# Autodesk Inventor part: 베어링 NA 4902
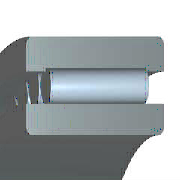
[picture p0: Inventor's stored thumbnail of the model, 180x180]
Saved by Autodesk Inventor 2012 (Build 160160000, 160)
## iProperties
IsCustomPart: 0
Manager: KYOUNG IL JANG
Company: 한국ATC센터
Created: 2009-02
Part Number: 베어링 NA 4902
Material: Steel, Mild
Description: 니들 롤러 베어링 - 경계 치수 및 공차
Document SubType Name: Modeling
Standard: KS B 2029
Standards Organization: KS
Language: ko-KR
Size Designation: NA 4902 - 15 x 28 x 13
Categories: <MemberInstance><Categories><Category DisplayName="샤프트 부품" InternalName="7f7aeb1f-a693-4053-b835-cee3144e0d98" Mnemonic="SHFT"><Category DisplayName="베어링" Inter
Density: 1 g/cm^3
Checked By: KYOUNG IL JANG
Vendor: CBT Solutions
Designer: KYOUNG IL JANG
Author: KYOUNG IL JANG
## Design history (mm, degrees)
revolve "본체" stored, may be unused: angle "d17" = 90 deg
revolve "롤러" stored, may be unused: angle "d18" = 90 deg
body "Solid1"
sketch "스케치"
  geometry: L1 (1.857, 11.5)-(11.143, 11.5); L2 (11.143, 11.5)-(11.143, 10); L3 (13, 10)-(0, 10); L4 (1.857, 10)-(1.857, 11.5); L5 (1.857, 10.75)-(11.143, 10.75); L6 (6.5, 10.75)-(6.5, 10); L7 (0, 7.5)-(13, 7.5); L8 (0, 14)-(13, 14); L9 (13, 7.5)-(13, 10); L10 (13, 11.35)-(13, 14); L11 (1.857, 11.35)-(0, 11.35); L12 (11.143, 11.35)-(13, 11.35); L13 (-6, 0)-(36, 0) reference; L14 (0, -1.9)-(0, 14.9) reference
  constraints: 24 end point, 8 point on line, 3 midpoint, 3 parallel, 3 perpendicular, 2 symmetric about line, 1 horizontal, 1 other
  dimensions: "d6" = 15 diameter of L7 L13 (= WD); "d7" = 20 diameter of L3 L13 (= KID1); "d8" = 28 diameter of L8 L13 (= BD); "d9" = 21.5 diameter of L6.start L13 (= 0.5 x WD + 0.5 x BD); "d10" = 22.7 diameter of L12 L13 (= 0.9 x BD + 0.9 x WD - 0.8 x KID1); "d11" = 23 diameter of L1 L13 (= BD + WD - KID1); "d12" = 1.85714 distance between parallel lines of L14 L4 (= 0.142857 x KB); "d13" = 13 distance between parallel lines of L14 L9 (= KB); "d14" = 11.14286 distance between parallel lines of L14 L2 (= 0.857143 x KB)
fillet "모깎기1" dims "d0" = 0.3 (= KRS)
pattern_circular "IDS_ARRAYROLLER[SIMPL:T]" dims angle "d2" = 360 deg
other parameters: "WD" = 15 [user parameter; used in 6 equation terms], "BD" = 28 [user parameter; used in 6 equation terms], "KB" = 13 [user parameter; used in 3 equation terms], "KID1" = 20 [user parameter; used in 4 equation terms], "KRS" = 0.3 [user parameter; used in 1 equation term], "d3" = 0, "d4" = 0, "d5" = 0, "d15" = 0, "d16" = 0, "BC0" = 1.37e+07 [user parameter], "WR" = 7.5 (= 0.5 x WD) [user parameter], "BBA" = 0 [user parameter], "BC" = 1.02e+07 [user parameter], "BR" = 14 (= 0.5 x BD) [user parameter]
